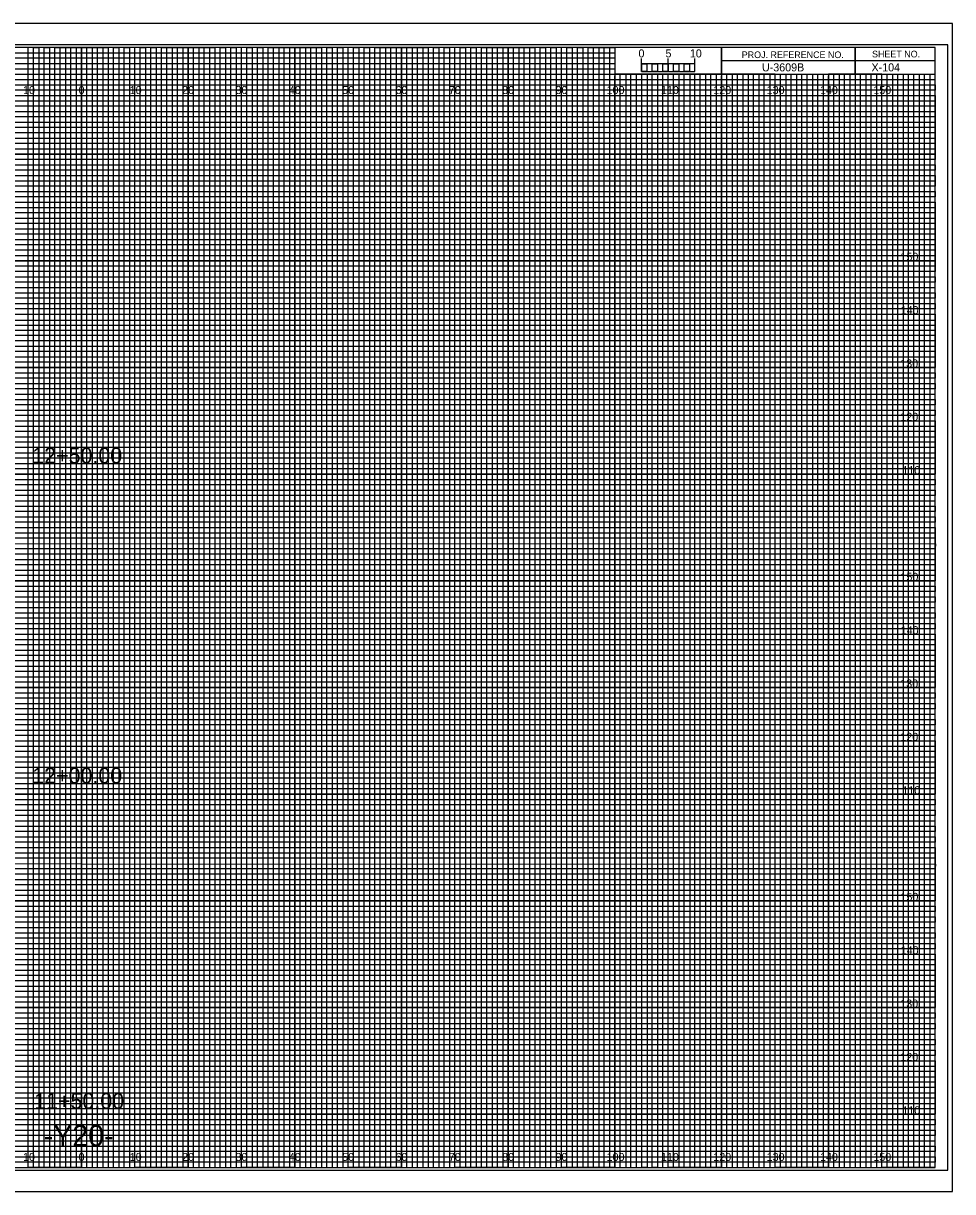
# Model space of a CAD drawing. Extents: x -13 to 323, y -5 to 2634.
# Drawn here: x 149.1 to 323.3, y 215.5 to 434.5 of the extents above; entities that cross this region are included whole.
import ezdxf

# ---------------------------------------------------------------- set-up
doc = ezdxf.new("R2010")
doc.units = 0
for name, color, linetype in [('Exist CMT Pavement', 7, 'Continuous'), ('Exist Cross Section Cell', 7, 'Continuous'), ('Exist XS Center Line Elevation Label', 7, 'Continuous'), ('Exist XS Ground Line', 7, 'Continuous'), ('Prop CMT Pvmt Course 1 Wedge', 7, 'Continuous'), ('Prop CMT Pvmt Course 2', 7, 'Continuous'), ('Prop CMT Pvmt Course 2 Wedge', 7, 'Continuous'), ('Prop CMT Pvmt Course 3', 7, 'Continuous'), ('Prop CMT Pvmt Course 3 Wedge', 7, 'Continuous'), ('Prop CMT Pvmt Surface', 7, 'Continuous'), ('Prop CMT Pvmt Wedge Surface 1', 7, 'Continuous'), ('Prop CMT Pvmt Wedge Surface 2', 7, 'Continuous'), ('Prop CMT Shld Paved Course 1', 7, 'Continuous'), ('Prop CMT Shld Paved Course 2', 7, 'Continuous'), ('Prop CMT Shld Paved Course 3', 7, 'Continuous'), ('Prop CMT Subgrade Earthwork', 7, 'Continuous'), ('Scratch_Level_0', 7, 'Continuous')]:
    doc.layers.add(name, color=color, linetype=linetype)

msp = doc.modelspace()

# ---------------------------------------------------------------- linework, layer by layer
at = {"layer": 'Exist XS Center Line Elevation Label'}
for points in [[(145, 220), (155, 220), (155, 430), (165, 430), (165, 220), (175, 220), (175, 430), (185, 430), (185, 220), (195, 220), (195, 430), (205, 430), (205, 220), (215, 220), (215, 430), (225, 430), (225, 220), (235, 220), (235, 430), (245, 430), (245, 220), (255, 220), (255, 430), (259.93, 430), (260, 430), (260, 425), (264.99, 425), (264.99, 220), (275, 220), (275, 425), (285, 425), (285, 220), (295, 220), (295, 425), (305, 425), (305, 220), (315, 220), (315, 425)], [(0, 425), (275, 425)], [(0, 405), (320, 405), (320, 415), (0, 415)], [(0, 385), (320, 385), (320, 395), (0, 395)], [(0, 365), (320, 365), (320, 375), (0, 375)], [(0, 345), (320, 345), (320, 355), (0, 355)], [(0, 325), (320, 325), (320, 335), (0, 335)], [(0, 305), (320, 305), (320, 315), (0, 315)], [(0, 285), (320, 285), (320, 295), (0, 295)], [(0, 265), (320, 265), (320, 275), (0, 275)], [(0, 245), (320, 245), (320, 255), (0, 255)], [(0, 225), (320, 225), (320, 235), (0, 235)]]:
    msp.add_lwpolyline(points, dxfattribs=at)
at = {"layer": 'Exist XS Ground Line'}
for p, q in [((150, 430), (140, 430)), ((150, 220), (150, 430)), ((170, 430), (160, 430)), ((160, 430), (160, 220)), ((170, 220), (170, 430)), ((190, 430), (180, 430)), ((180, 430), (180, 220)), ((190, 220), (190, 430)), ((210, 430), (200, 430)), ((200, 430), (200, 220)), ((210, 220), (210, 430)), ((230, 430), (220, 430)), ((220, 430), (220, 220)), ((230, 220), (230, 430)), ((250, 430), (240, 430)), ((240, 430), (240, 220)), ((250, 220), (250, 430)), ((260, 430), (260, 220)), ((270, 220), (270, 425)), ((290, 425), (280, 425)), ((280, 425), (280, 220)), ((290, 220), (290, 425)), ((310, 425), (300, 425)), ((300, 425), (300, 220)), ((310, 220), (310, 425)), ((160, 220), (150, 220)), ((180, 220), (170, 220)), ((200, 220), (190, 220)), ((220, 220), (210, 220)), ((240, 220), (230, 220)), ((260, 220), (250, 220)), ((280, 220), (270, 220)), ((300, 220), (290, 220)), ((320, 220), (310, 220)), ((320, 220), (320, 220))]:
    msp.add_line(p, q, dxfattribs=at)
for points in [[(0, 420), (320, 420), (320, 410), (0, 410)], [(0, 400), (320, 400), (320, 390), (0, 390)], [(0, 380), (320, 380), (320, 370), (0, 370)], [(0, 360), (320, 360), (320, 350), (0, 350)], [(0, 340), (320, 340), (320, 330), (0, 330)], [(0, 320), (320, 320), (320, 310), (0, 310)], [(0, 300), (320, 300), (320, 290), (0, 290)], [(0, 280), (320, 280), (320, 270), (0, 270)], [(0, 260), (320, 260), (320, 250), (0, 250)], [(0, 240), (320, 240), (320, 230), (0, 230)]]:
    msp.add_lwpolyline(points, dxfattribs=at)
at = {"layer": 'Prop CMT Pvmt Course 1 Wedge'}
for p, q in [((323.3, 434.5), (-13.4, 434.5)), ((-13.4, 215.5), (323.3, 215.5))]:
    msp.add_line(p, q, dxfattribs=at)
at = {"layer": 'Prop CMT Pvmt Course 2'}
msp.add_lwpolyline([(-13.4, 215.5), (323.3, 215.5), (323.3, 434.5), (-13.4, 434.5)], close=True, dxfattribs=at)
at = {"layer": 'Prop CMT Pvmt Course 3'}
msp.add_lwpolyline([(-10.8, 219.5), (322.4, 219.5), (322.4, 430.5), (-10.8, 430.5)], close=True, dxfattribs=at)
at = {"layer": 'Prop CMT Shld Paved Course 1'}
for p, q in [((305, 430), (305, 425)), ((305, 425), (305, 430)), ((280, 427.5), (280, 425)), ((320, 427.49), (280, 427.49)), ((280, 425), (320, 425))]:
    msp.add_line(p, q, dxfattribs=at)
for points in [[(320, 430), (0, 430), (0, 220), (320, 220)], [(280, 430), (260, 430), (260, 425.03), (280, 425.03)], [(320, 430), (280, 430), (280, 425), (320, 425)]]:
    msp.add_lwpolyline(points, close=True, dxfattribs=at)
at = {"layer": 'Prop CMT Shld Paved Course 2'}
for p, q in [((267, 425), (266.01, 425)), ((266.01, 425), (266.01, 220)), ((267, 220), (267, 425)), ((269, 425), (268, 425)), ((268, 425), (268, 220)), ((269, 220), (269, 425)), ((266.01, 220), (265, 220)), ((268, 220), (267, 220))]:
    msp.add_line(p, q, dxfattribs=at)
for points in [[(150, 220), (151, 220), (151, 430), (152, 430), (152, 220)], [(152, 220), (153, 220), (153, 430), (154, 430), (154, 220)], [(155, 220), (156, 220), (156, 430), (157, 430), (157, 220)], [(157, 220), (158, 220), (158, 430), (159, 430), (159, 220)], [(160, 220), (161, 220), (161, 430), (162, 430), (162, 220)], [(162, 220), (163, 220), (163, 430), (164, 430), (164, 220)], [(165, 220), (166, 220), (166, 430), (167, 430), (167, 220)], [(167, 220), (168, 220), (168, 430), (169, 430), (169, 220)], [(170, 220), (171, 220), (171, 430), (172, 430), (172, 220)], [(172, 220), (173, 220), (173, 430), (174, 430), (174, 220)], [(175, 220), (176, 220), (176, 430), (177, 430), (177, 220)], [(177, 220), (178, 220), (178, 430), (179, 430), (179, 220)], [(180, 220), (181, 220), (181, 430), (182, 430), (182, 220)], [(182, 220), (183, 220), (183, 430), (184, 430), (184, 220)], [(185, 220), (186, 220), (186, 430), (187, 430), (187, 220)], [(187, 220), (188, 220), (188, 430), (189, 430), (189, 220)], [(190, 220), (191, 220), (191, 430), (192, 430), (192, 220)], [(192, 220), (193, 220), (193, 430), (194, 430), (194, 220)], [(195, 220), (196, 220), (196, 430), (197, 430), (197, 220)], [(197, 220), (198, 220), (198, 430), (199, 430), (199, 220)], [(200, 220), (201, 220), (201, 430), (202, 430), (202, 220)], [(202, 220), (203, 220), (203, 430), (204, 430), (204, 220)], [(205, 220), (206, 220), (206, 430), (207, 430), (207, 220)], [(207, 220), (208, 220), (208, 430), (209, 430), (209, 220)], [(210, 220), (211, 220), (211, 430), (212, 430), (212, 220)], [(212, 220), (213, 220), (213, 430), (214, 430), (214, 220)], [(215, 220), (216, 220), (216, 430), (217, 430), (217, 220)], [(217, 220), (218, 220), (218, 430), (219, 430), (219, 220)], [(220, 220), (221, 220), (221, 430), (222, 430), (222, 220)], [(222, 220), (223, 220), (223, 430), (224, 430), (224, 220)], [(225, 220), (226, 220), (226, 430), (227, 430), (227, 220)], [(227, 220), (228, 220), (228, 430), (229, 430), (229, 220)], [(230, 220), (231, 220), (231, 430), (232, 430), (232, 220)], [(232, 220), (233, 220), (233, 430), (234, 430), (234, 220)], [(235, 220), (236, 220), (236, 430), (237, 430), (237, 220)], [(237, 220), (238, 220), (238, 430), (239, 430), (239, 220)], [(240, 220), (241, 220), (241, 430), (242, 430), (242, 220)], [(242, 220), (243, 220), (243, 430), (244, 430), (244, 220)], [(245, 220), (246, 220), (246, 430), (247, 430), (247, 220)], [(247, 220), (248, 220), (248, 430), (249, 430), (249, 220)], [(250, 220), (251, 220), (251, 430), (252, 430), (252, 220)], [(252, 220), (253, 220), (253, 430), (254, 430), (254, 220)], [(255, 220), (256, 220), (256, 430), (257, 430), (257, 220)], [(257, 220), (258, 220), (258, 430), (259, 430), (259, 220)], [(260, 220), (261, 220), (261, 425), (262.02, 425), (262.02, 220)], [(262, 220), (263, 220), (263, 425), (263.99, 425), (263.99, 220)], [(270, 220), (270.98, 220), (270.98, 425), (272, 425), (272, 220)], [(272, 220), (273, 220), (273, 425), (274.05, 425), (274.05, 220)], [(275, 220), (276, 220), (276, 425), (277, 425), (277, 220)], [(277, 220), (278, 220), (278, 425), (279, 425), (279, 220)], [(280, 220), (281, 220), (281, 425), (282, 425), (282, 220)], [(282, 220), (283, 220), (283, 425), (284, 425), (284, 220)], [(285, 220), (286, 220), (286, 425), (287, 425), (287, 220)], [(287, 220), (288, 220), (288, 425), (289, 425), (289, 220)], [(290, 220), (291, 220), (291, 425), (292, 425), (292, 220)], [(292, 220), (293, 220), (293, 425), (294, 425), (294, 220)], [(295, 220), (296, 220), (296, 425), (297, 425), (297, 220)], [(297, 220), (298, 220), (298, 425), (299, 425), (299, 220)], [(300, 220), (301, 220), (301, 425), (302, 425), (302, 220)], [(302, 220), (303, 220), (303, 425), (304, 425), (304, 220)], [(305, 220), (306, 220), (306, 425), (307, 425), (307, 220)], [(307, 220), (308, 220), (308, 425), (309, 425), (309, 220)], [(310, 220), (311, 220), (311, 425), (312, 425), (312, 220)], [(312, 220), (313, 220), (313, 425), (314, 425), (314, 220)], [(315, 220), (316, 220), (316, 425), (317, 425), (317, 220)], [(317, 220), (318, 220), (318, 425), (319, 425), (319, 220)]]:
    msp.add_lwpolyline(points, dxfattribs=at)
at = {"layer": 'Prop CMT Shld Paved Course 3'}
for p, q in [((265, 425.49), (265, 427.9)), ((265, 426.9), (265, 427.9)), ((270, 425.49), (270, 427.9)), ((275, 425.49), (275, 427.9)), ((275, 426.9), (275, 427.9))]:
    msp.add_line(p, q, dxfattribs=at)
for points in [[(275, 426.9), (265, 426.9), (265, 425.49), (275, 425.49)], [(265, 426.9), (266, 426.9), (266, 425.49), (265, 425.49)], [(267, 426.9), (268, 426.9), (268, 425.49), (267, 425.49)], [(269, 426.9), (270, 426.9), (270, 425.49), (269, 425.49)], [(271, 426.9), (272, 426.9), (272, 425.49), (271, 425.49)], [(273, 426.9), (274, 426.9), (274, 425.49), (273, 425.49)]]:
    msp.add_lwpolyline(points, close=True, dxfattribs=at)
at = {"layer": 'Prop CMT Subgrade Earthwork'}
for p, q in [((150, 220), (150, 430)), ((160, 220), (160, 430)), ((170, 220), (170, 430)), ((180, 220), (180, 430)), ((190, 220), (190, 430)), ((200, 220), (200, 430)), ((210, 220), (210, 430)), ((220, 220), (220, 430)), ((230, 220), (230, 430)), ((240, 220), (240, 430)), ((250, 220), (250, 430)), ((260, 220), (260, 424.69)), ((270, 220), (270, 424.69)), ((280, 220), (280, 424.69)), ((290, 220), (290, 424.69)), ((300, 220), (300, 424.69)), ((310, 220), (310, 424.69)), ((0, 420), (320, 420)), ((0, 410), (320, 410)), ((0, 400), (320, 400)), ((0, 390), (320, 390)), ((0, 380), (320, 380)), ((0, 370), (320, 370)), ((0, 360), (320, 360)), ((0, 350), (320, 350)), ((0, 340), (320, 340)), ((0, 330), (320, 330)), ((0, 320), (320, 320)), ((0, 310), (320, 310)), ((0, 300), (320, 300)), ((0, 290), (320, 290)), ((0, 280), (320, 280)), ((0, 270), (320, 270)), ((0, 260), (320, 260)), ((0, 250), (320, 250)), ((0, 240), (320, 240)), ((0, 230), (320, 230))]:
    msp.add_line(p, q, dxfattribs=at)
at = {"layer": 'Scratch_Level_0'}
for p, q in [((0, 429), (260, 429)), ((260, 427.98), (0, 427.98)), ((260, 429), (260, 427.98)), ((0, 427), (260, 427)), ((260, 425.89), (0, 425.89)), ((260, 427), (260, 425.89)), ((0, 424), (320, 424))]:
    msp.add_line(p, q, dxfattribs=at)
for points in [[(0, 423), (270, 423), (320, 423), (320, 422), (0, 422)], [(0, 421), (320, 421), (320, 419), (0, 419)], [(0, 418), (320, 418), (320, 417), (0, 416.98)], [(0, 416), (320, 416), (320, 414), (0, 414)], [(0, 413), (320, 413), (320, 412), (0, 412)], [(0, 411), (320, 411), (320, 409), (0, 409)], [(0, 408), (320, 408), (320, 407), (0, 407)], [(0, 406), (320, 406), (320, 404), (0, 404)], [(0, 403), (320, 403), (320, 402), (0, 402)], [(0, 401), (320, 401), (320, 399), (0, 399)], [(0, 398), (320, 398), (320, 397), (0, 397)], [(0, 396), (320, 396), (320, 393.95), (320, 393), (320, 392), (0, 392)], [(0, 394), (320, 394), (320, 393), (0, 393)], [(0, 391), (320, 391), (320, 389), (0, 389.03)], [(0, 389.03), (320, 389), (320, 388), (0, 388)], [(0, 387), (320, 387), (320, 386), (0, 386)], [(0, 384), (320, 384), (320, 383), (0, 383)], [(0, 382), (320, 382), (320, 381), (0, 381)], [(-0.07, 378.89), (320, 378.89), (320, 377.88), (-0.07, 377.88)], [(0, 377), (320, 377), (320, 376), (0, 376)], [(0, 374), (320, 374), (320, 373), (0, 373)], [(0, 372), (320, 372), (320, 371), (0, 371)], [(0, 369), (320, 369), (320, 368), (0, 368)], [(0, 367), (320, 367), (320, 366), (0, 366)], [(0, 364), (320, 364), (320, 363), (0, 363)], [(0, 362), (320, 362), (320, 361), (0, 361)], [(0, 359), (320, 359), (319.99, 357.98), (0, 358)], [(0, 357), (320, 357), (320, 356), (0, 356)], [(0, 354), (320, 354), (320, 353), (0, 353)], [(0, 352), (320, 352), (320, 351), (0, 351)], [(0, 349), (320, 349), (320, 348), (0, 348)], [(0, 347), (320, 347), (320, 346), (0, 346)], [(0, 344), (320, 344), (320, 343), (0, 343)], [(0, 342), (320, 342), (320, 341), (0, 341)], [(0, 339), (320, 339), (320, 338), (0, 338)], [(0, 336.99), (320.07, 336.91), (320, 336), (0, 336)], [(0, 334), (320, 334), (320, 333), (0, 333)], [(0, 332), (320, 332), (320, 331), (0, 331)], [(0, 329), (320, 329), (320, 328), (0, 328)], [(0, 327), (320, 327), (320, 326), (0, 326)], [(0, 324), (320, 324), (320, 323), (0, 323)], [(0, 322), (320, 322), (320, 321), (0, 321)], [(0, 319), (320, 319), (320, 318), (0, 318)], [(0, 317), (320, 317), (320, 316), (0, 316)], [(0, 314), (320, 314), (320, 313), (0, 313)], [(0, 312), (320, 312), (320, 311), (0, 311)], [(0, 309), (320, 309), (320, 308), (0, 308)], [(0, 307), (320, 307), (320, 306), (0, 306)], [(0, 304), (320, 304), (320, 303), (0, 303)], [(0, 302), (320, 302), (320, 301), (0, 301)], [(0, 299), (320, 299), (319.99, 297.98), (0, 298)], [(0, 297), (320, 297), (320, 296), (0, 296)], [(0, 294), (320, 294), (320, 293), (0, 293)], [(0, 292), (320, 292), (320, 291), (0, 291)], [(0, 289), (320, 289), (320, 288), (0, 288)], [(0, 287), (320, 287), (320, 286), (0, 286)], [(0, 284), (320, 284), (320, 283), (0, 283)], [(0, 282), (320, 282), (320, 281), (0, 281)], [(0, 279), (320, 279), (320, 278), (0, 278)], [(0, 276.99), (320.07, 276.91), (320, 276), (0, 276)], [(0, 274), (320, 274), (320, 273), (0, 273)], [(0, 272), (320, 272), (320, 271), (0, 271)], [(0, 269), (320, 269), (320, 268), (0, 268)], [(0, 267), (320, 267), (320, 266), (0, 266)], [(0, 264), (320, 264), (320, 263), (0, 263)], [(0, 262), (320, 262), (320, 261), (0, 261)], [(0, 259), (320, 259), (320, 258), (0, 258)], [(0, 257), (320, 257), (320, 256), (0, 256)], [(0, 254), (320, 254), (320, 253), (0, 253)], [(0, 252), (320, 252), (320, 251), (0, 251)], [(0, 249), (320, 249), (320, 248), (0, 248)], [(0, 247), (320, 247), (320, 246), (0, 246)], [(0, 244), (320, 244), (320, 243), (0, 243)], [(0, 242), (320, 242), (320, 241), (0, 241)], [(0, 239), (320, 239), (320, 238), (0, 238)], [(0, 237), (320, 237), (320, 236), (0, 236)], [(0, 234), (320, 234), (320, 233), (0, 233)], [(0, 232), (320, 232), (320, 231), (0, 231)], [(0, 229), (320, 229), (320, 228), (0, 228)], [(0, 227), (320, 227), (320, 226), (0, 226)], [(0, 224), (320, 224), (320, 223), (0, 223)], [(0, 222), (320, 222), (320, 221), (0, 221)]]:
    msp.add_lwpolyline(points, dxfattribs=at)

# ---------------------------------------------------------------- texts
at = {"layer": 'Exist CMT Pavement'}
msp.add_text('X-104', height=1.5, dxfattribs=at).set_placement((308.09, 425.5))
at = {"layer": 'Exist Cross Section Cell'}
for s, p in [('10', (149.04, 421.25)), ('0', (159.45, 421.25)), ('0', (159.45, 421.25)), ('10', (169.04, 421.25)), ('20', (178.86, 421.25)), ('30', (188.86, 421.25)), ('40', (198.86, 421.25)), ('50', (208.86, 421.25)), ('60', (218.86, 421.25)), ('70', (228.86, 421.25)), ('80', (238.86, 421.25)), ('90', (248.86, 421.25)), ('100', (258.44, 421.25)), ('110', (268.62, 421.25)), ('120', (278.44, 421.25)), ('130', (288.44, 421.25)), ('140', (298.44, 421.25)), ('150', (308.44, 421.25)), ('10', (149.04, 221.25)), ('0', (159.45, 221.25)), ('0', (159.45, 221.25)), ('10', (169.04, 221.25)), ('20', (178.86, 221.25)), ('30', (188.86, 221.25)), ('40', (198.86, 221.25)), ('50', (208.86, 221.25)), ('60', (218.86, 221.25)), ('70', (228.86, 221.25)), ('80', (238.86, 221.25)), ('90', (248.86, 221.25)), ('100', (258.44, 221.25)), ('110', (268.62, 221.25)), ('120', (278.44, 221.25)), ('130', (288.44, 221.25)), ('140', (298.44, 221.25)), ('150', (308.44, 221.25))]:
    msp.add_text(s, height=1.5, dxfattribs=at).set_placement(p)
at = {"layer": 'Prop CMT Pvmt Course 2 Wedge'}
for s, p in [('150', (313.52, 390)), ('140', (313.57, 380)), ('130', (313.49, 370)), ('120', (313.5, 360)), ('110', (313.88, 350)), ('150', (313.52, 330)), ('140', (313.57, 320)), ('130', (313.49, 310)), ('120', (313.5, 300)), ('110', (313.88, 290)), ('150', (313.52, 270)), ('140', (313.57, 260)), ('130', (313.49, 250)), ('120', (313.5, 240)), ('110', (313.88, 230))]:
    msp.add_text(s, height=1.5, dxfattribs=at).set_placement(p)
at = {"layer": 'Prop CMT Pvmt Course 3 Wedge'}
for s, p in [('12+50.00', (150.77, 352)), ('12+00.00', (150.77, 292)), ('11+50.00', (151.13, 231))]:
    msp.add_text(s, height=3, dxfattribs=at).set_placement(p)
at = {"layer": 'Prop CMT Pvmt Surface'}
msp.add_text('U-3609B', height=1.5, dxfattribs=at).set_placement((287.56, 425.5))
at = {"layer": 'Prop CMT Pvmt Wedge Surface 1'}
msp.add_text('-Y20-', height=4, dxfattribs=at).set_placement((152.93, 224))
at = {"layer": 'Prop CMT Pvmt Wedge Surface 2'}
for s, p in [('5', (269.47, 428.12)), ('10', (274.04, 428.12))]:
    msp.add_text(s, height=1.5, dxfattribs=at).set_placement(p)
at = {"layer": 'Prop CMT Shld Paved Course 1'}
for s, p in [('PROJ. REFERENCE NO.', (283.77, 427.99)), ('SHEET NO.', (308.19, 428.12))]:
    msp.add_text(s, height=1.25, dxfattribs=at).set_placement(p)
at = {"layer": 'Prop CMT Shld Paved Course 3'}
msp.add_text('0', height=1.5, dxfattribs=at).set_placement((264.41, 428.12))

doc.saveas('drawing.dxf')
